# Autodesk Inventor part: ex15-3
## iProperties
Created: 2006-03
Part Number: ex15-3
Document SubType Name: Modeling
Designer: Elise Moss
Author: Elise Moss
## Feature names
1. Extrusion1
2. Hole1
3. Shell1
4. Chamfer1
